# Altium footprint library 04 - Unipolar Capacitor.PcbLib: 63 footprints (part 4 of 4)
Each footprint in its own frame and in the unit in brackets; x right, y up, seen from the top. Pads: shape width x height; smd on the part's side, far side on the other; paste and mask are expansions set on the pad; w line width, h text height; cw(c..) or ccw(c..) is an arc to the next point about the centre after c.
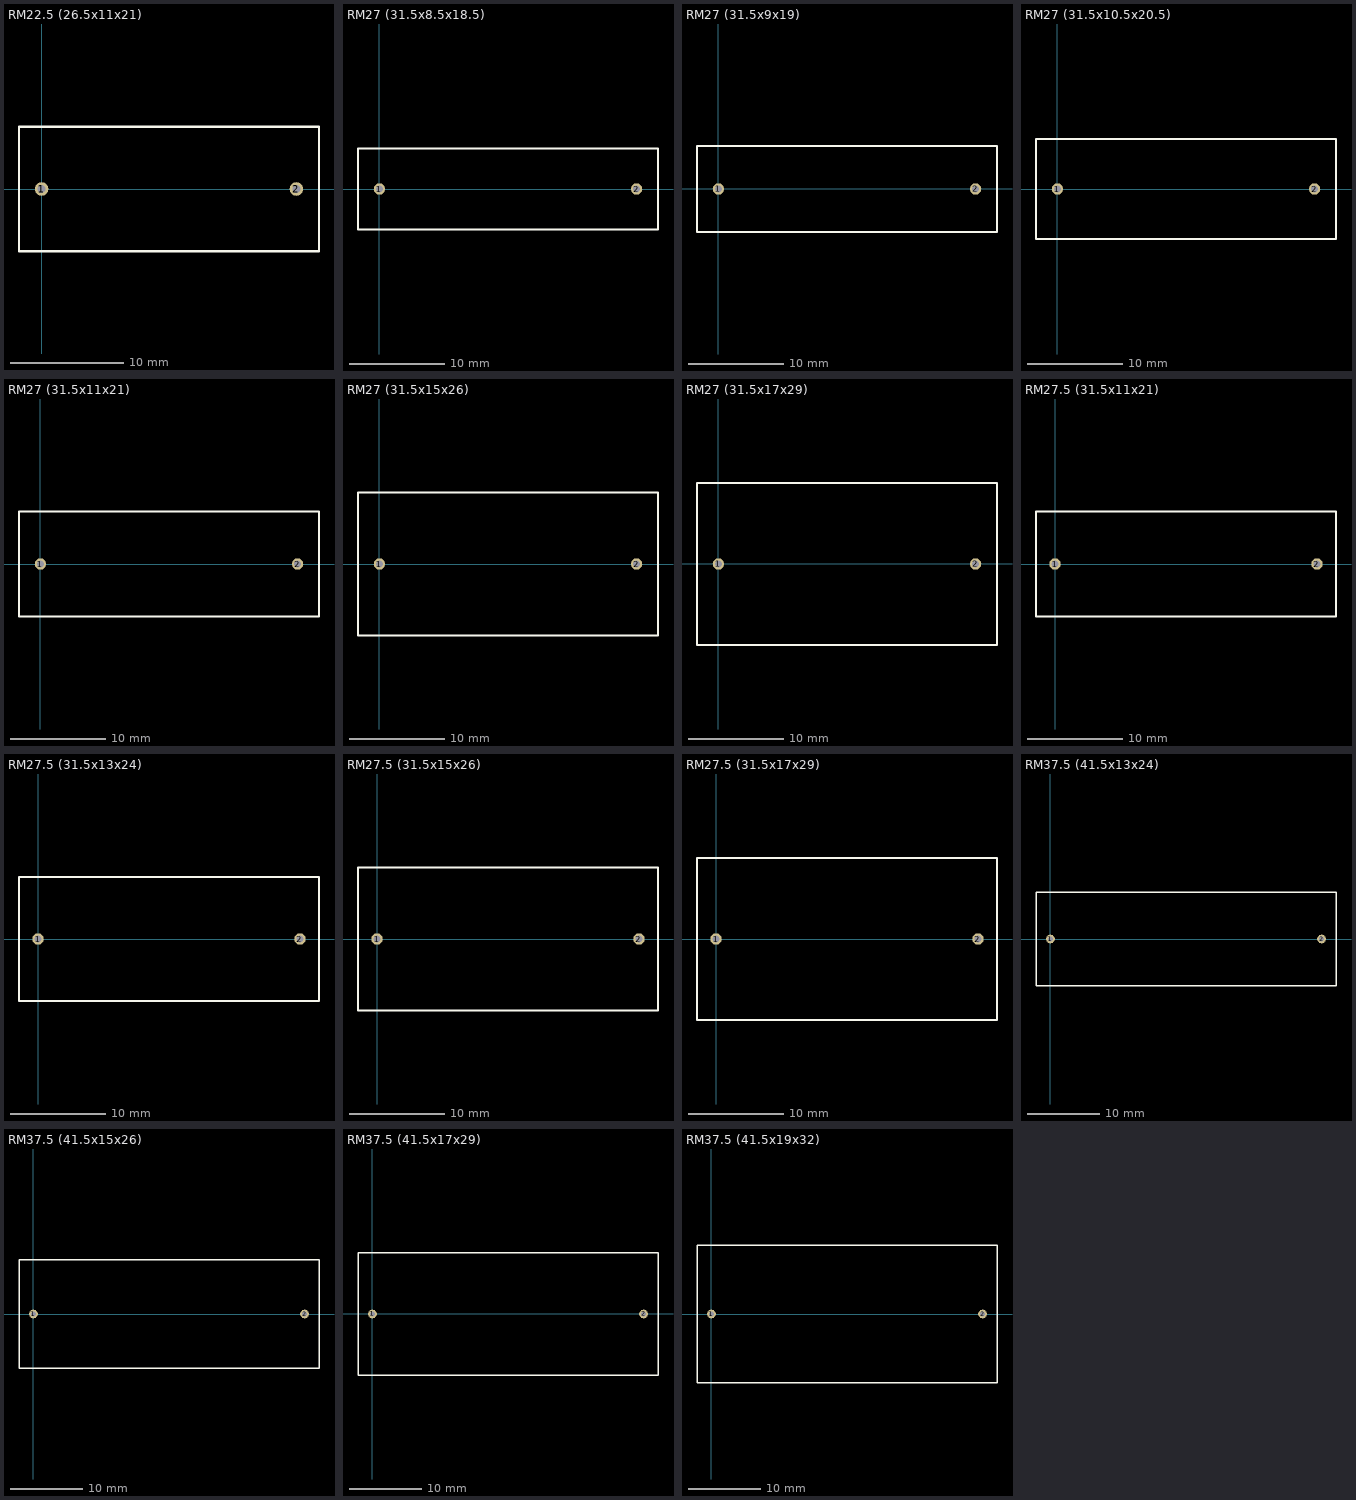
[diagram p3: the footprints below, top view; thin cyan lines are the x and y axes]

## RM22.5 (26.5x11x21) [mm] "Radial Thumb Capacitor"
height 21
pads (2):
  round 1.2 hole 0.7: 1(0,0) 2(22.5,0)
Top Overlay:
  lines w0.2: -2,-5.5 -2,5.5 24.5,5.5 24.5,-5.5 -2,-5.5

## RM27 (31.5x8.5x18.5) [mm] "Radial Thumb Capacitor"
height 18.5
pads (2):
  round 1.2 hole 0.7: 1(0,0) 2(27,0)
Top Overlay:
  lines w0.2: -2.25,-4.25 -2.25,4.25 29.25,4.25 29.25,-4.25 -2.25,-4.25

## RM27 (31.5x9x19) [mm] "Radial Thumb Capacitor"
height 19
pads (2):
  round 1.2 hole 0.7: 1(0,0) 2(27,0)
Top Overlay:
  lines w0.2: -2.25,-4.5 -2.25,4.5 29.25,4.5 29.25,-4.5 -2.25,-4.5

## RM27 (31.5x10.5x20.5) [mm] "Radial Thumb Capacitor"
height 20.5
pads (2):
  round 1.2 hole 0.7: 1(0,0) 2(27,0)
Top Overlay:
  lines w0.2: -2.25,-5.25 29.25,-5.25 29.25,5.25 -2.25,5.25 -2.25,-5.25

## RM27 (31.5x11x21) [mm] "Radial Thumb Capacitor"
height 21
pads (2):
  round 1.2 hole 0.7: 1(0,0) 2(27,0)
Top Overlay:
  lines w0.2: -2.25,-5.5 -2.25,5.5 29.25,5.5 29.25,-5.5 -2.25,-5.5

## RM27 (31.5x15x26) [mm] "Radial Thumb Capacitor"
height 26
pads (2):
  round 1.2 hole 0.7: 1(0,0) 2(27,0)
Top Overlay:
  lines w0.2: -2.25,-7.5 29.25,-7.5 29.25,7.5 -2.25,7.5 -2.25,-7.5

## RM27 (31.5x17x29) [mm] "Radial Thumb Capacitor"
height 29
pads (2):
  round 1.2 hole 0.7: 1(0,0) 2(27,0)
Top Overlay:
  lines w0.2: -2.25,-8.5 29.25,-8.5 29.25,8.5 -2.25,8.5 -2.25,-8.5

## RM27.5 (31.5x11x21) [mm] "Radial Thumb Capacitor"
height 21
pads (2):
  round 1.2 hole 0.7: 1(0,0) 2(27.5,0)
Top Overlay:
  lines w0.2: -2,-5.5 29.5,-5.5 29.5,5.5 -2,5.5 -2,-5.5

## RM27.5 (31.5x13x24) [mm] "Radial Thumb Capacitor"
height 24
pads (2):
  round 1.2 hole 0.7: 1(0,0) 2(27.5,0)
Top Overlay:
  lines w0.2: -2,-6.5 -2,6.5 29.5,6.5 29.5,-6.5 -2,-6.5

## RM27.5 (31.5x15x26) [mm] "Radial Thumb Capacitor"
height 26
pads (2):
  round 1.2 hole 0.7: 1(0,0) 2(27.5,0)
Top Overlay:
  lines w0.2: -2,-7.5 -2,7.5 29.5,7.5 29.5,-7.5 -2,-7.5

## RM27.5 (31.5x17x29) [mm] "Radial Thumb Capacitor"
height 29
pads (2):
  round 1.2 hole 0.7: 1(0,0) 2(27.5,0)
Top Overlay:
  lines w0.2: -2,-8.5 29.5,-8.5 29.5,8.5 -2,8.5 -2,-8.5

## RM37.5 (41.5x13x24) [mm] "Radial Thumb Capacitor"
height 24
pads (2):
  round 1.2 hole 0.7: 1(0,0) 2(37.5,0)
Top Overlay:
  lines w0.2: -2,-6.5 -2,6.5 39.5,6.5 39.5,-6.5 -2,-6.5

## RM37.5 (41.5x15x26) [mm] "Radial Thumb Capacitor"
height 26
pads (2):
  round 1.2 hole 0.7: 1(0,0) 2(37.5,0)
Top Overlay:
  lines w0.2: -2,-7.5 -2,7.5 39.5,7.5 39.5,-7.5 -2,-7.5

## RM37.5 (41.5x17x29) [mm] "Radial Thumb Capacitor"
height 29
pads (2):
  round 1.2 hole 0.7: 1(0,0) 2(37.5,0)
Top Overlay:
  lines w0.2: -2,-8.5 -2,8.5 39.5,8.5 39.5,-8.5 -2,-8.5

## RM37.5 (41.5x19x32) [mm] "Radial Thumb Capacitor"
height 32
pads (2):
  round 1.2 hole 0.7: 1(0,0) 2(37.5,0)
Top Overlay:
  lines w0.2: -2,-9.5 39.5,-9.5 39.5,9.5 -2,9.5 -2,-9.5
